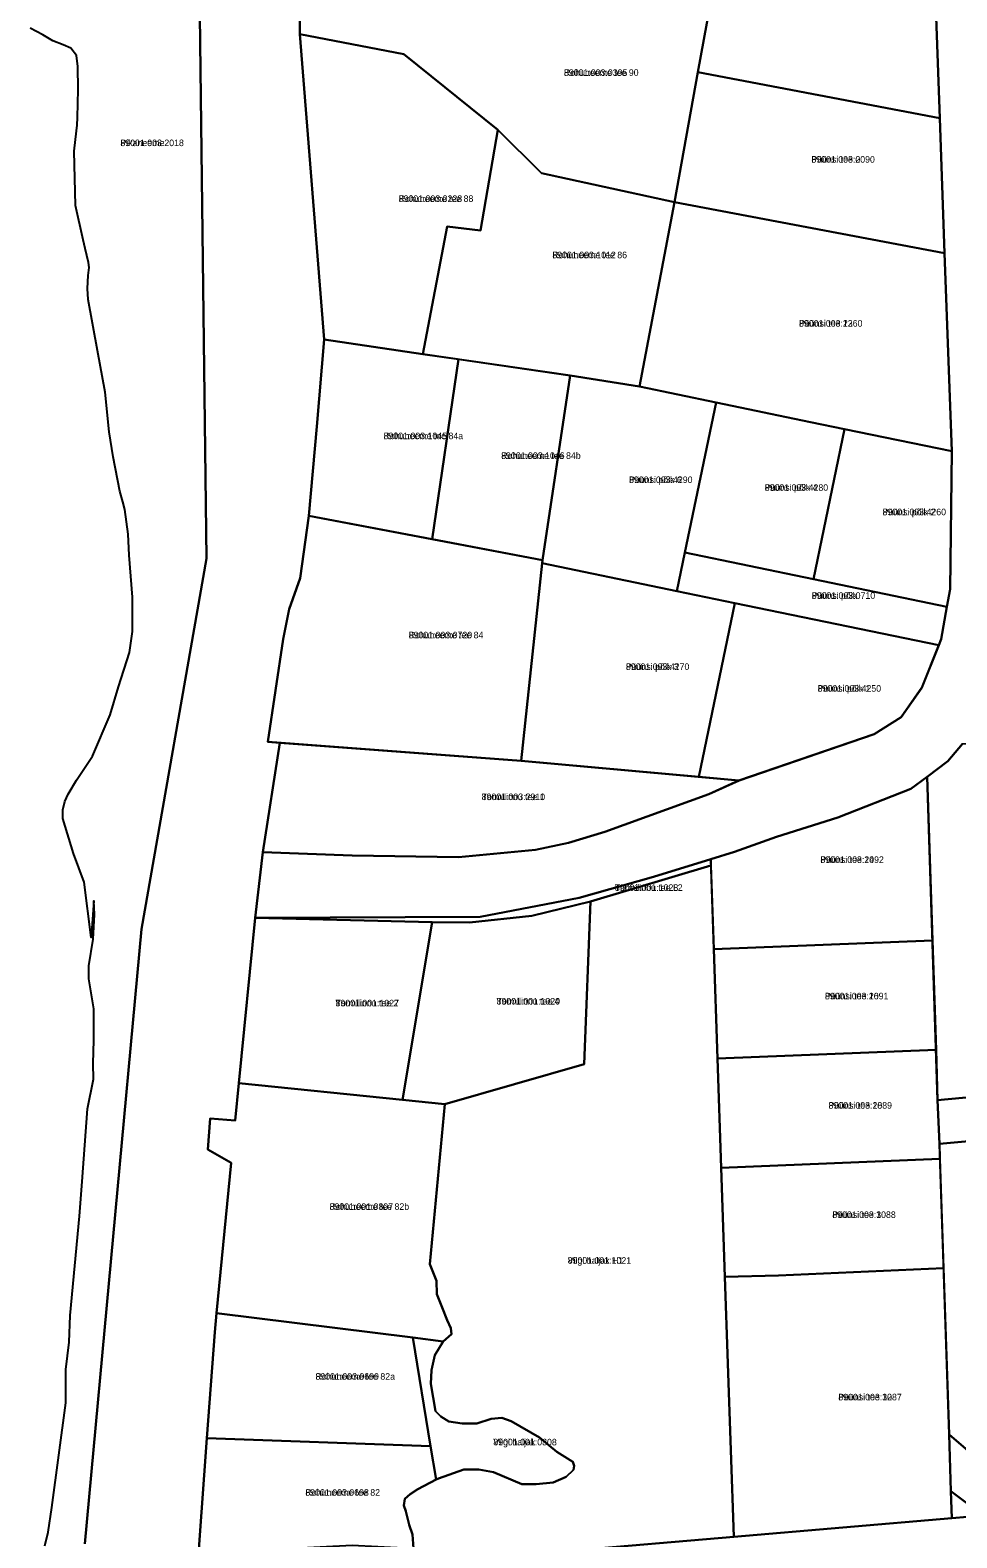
# Model space of a CAD drawing. Extents: x 526849 to 562296, y 6591741 to 6618546.
# Drawn here: x 544904.7 to 545116.6, y 6601222.5 to 6601567.1 of the extents above; entities that cross this region are included whole.
import ezdxf

# ---------------------------------------------------------------- set-up
doc = ezdxf.new("R2010")
doc.units = 0
for name, color, linetype in [('L_AADRESS', 7, 'Continuous'), ('PIIR', 7, 'Continuous'), ('TUNNUS', 7, 'Continuous')]:
    doc.layers.add(name, color=color, linetype=linetype)

msp = doc.modelspace()

# ---------------------------------------------------------------- linework, layer by layer
at = {"layer": 'PIIR'}
for points in [[(544917.24, 6601221.09), (544930.18, 6601361.63), (544945.05, 6601446.36), (544943.56, 6601570.5), (544945.36, 6601601.21), (544952.42, 6601687.05), (544958.45, 6601722.95), (544953.66, 6601829.01)], [(544953.66, 6601829.01), (544958.45, 6601722.95), (544952.42, 6601687.05), (544945.36, 6601601.21), (544943.56, 6601570.5), (544945.05, 6601446.36), (544930.18, 6601361.63), (544917.24, 6601221.09)], [(545117.87, 6601403.98), (545114.48, 6601400.03), (545109.74, 6601396.48), (545106.06, 6601393.72), (545089.33, 6601387.17), (545075.37, 6601382.73), (545065.77, 6601379.33), (545060.31, 6601377.63), (545047.2, 6601373.59), (545030.21, 6601368.81), (545007.59, 6601364.42), (544956.17, 6601364.26), (544957.94, 6601379.21), (544978.37, 6601378.47), (545002.65, 6601378.06), (545020.24, 6601379.81), (545027.77, 6601381.36), (545036.06, 6601383.86), (545059.87, 6601392.51), (545066.78, 6601395.64), (545097.69, 6601406.24), (545103.86, 6601410.1), (545108.55, 6601416.84), (545112.45, 6601426.54), (545113.01, 6601427.95), (545114.3, 6601435.35), (545115, 6601439.34), (545115.38, 6601470.87), (545113.73, 6601516.18), (545112.65, 6601547.05), (545111.16, 6601589.11)], [(544966.24, 6601585.53), (544966.36, 6601566.24), (544971.94, 6601496.4), (544970.29, 6601476.52), (544968.44, 6601456.13), (544966.44, 6601441.84), (544963.92, 6601434.79), (544962.57, 6601427.94), (544959.08, 6601404.43), (544961.78, 6601404.22), (544957.94, 6601379.21), (544956.17, 6601364.26), (544952.47, 6601326.4), (544951.62, 6601317.89), (544945.91, 6601318.37), (544945.35, 6601311.3), (544950.69, 6601308.22), (544947.36, 6601273.83), (544946.95, 6601269.54), (544945.15, 6601245.31), (544943.26, 6601219.91)], [(544908.09, 6601220.66), (544908.82, 6601223.77), (544909.67, 6601229.43), (544912.9, 6601253.33), (544912.89, 6601260.97), (544913.66, 6601267.2), (544913.88, 6601273.36), (544916.05, 6601296.03), (544916.62, 6601303.94), (544917.88, 6601320.54), (544919.24, 6601327.36), (544919.11, 6601330.92), (544919.33, 6601336.28), (544919.26, 6601343.45), (544918.14, 6601350.31), (544918.13, 6601353.25), (544919.15, 6601359.33), (544919.48, 6601364.97), (544919.32, 6601368.1), (544918.7, 6601359.74), (544917.12, 6601372.36), (544914.68, 6601378.96), (544912.21, 6601386.96), (544912.23, 6601388.89), (544912.64, 6601390.83), (544913.39, 6601392.49), (544915.3, 6601395.68), (544918.98, 6601401.21), (544923.04, 6601410.65), (544924.97, 6601417.03), (544927.41, 6601424.86), (544928.16, 6601429.69), (544928.11, 6601437.54), (544927.37, 6601447.15), (544927.18, 6601451.97), (544926.35, 6601457.56), (544925.89, 6601459.36), (544925.25, 6601461.8), (544923.73, 6601469.64), (544922.79, 6601475.34), (544921.89, 6601484.37), (544920.1, 6601493.91), (544918, 6601505.57), (544917.85, 6601508.09), (544917.99, 6601511.05), (544918.21, 6601512.87), (544918.11, 6601514.03), (544917.32, 6601517.21), (544916.86, 6601519.24), (544915.09, 6601527.07), (544914.8, 6601539.48), (544915.33, 6601544.11), (544915.48, 6601545.46), (544915.54, 6601547.19), (544915.75, 6601553.6), (544915.67, 6601558.83), (544915.32, 6601561.35), (544914, 6601563.04), (544912.32, 6601563.83), (544909.89, 6601564.68), (544907.61, 6601566.07), (544904.74, 6601567.6)], [(544992.36, 6601220.04), (544992.14, 6601223.25), (544991.35, 6601225.46), (544990.63, 6601228.63), (544990.17, 6601229.89), (544990.39, 6601231.43), (544991.57, 6601232.51), (544993.38, 6601233.66), (544997.52, 6601235.83), (544998.1, 6601236.08), (545003.89, 6601238.09), (545007.33, 6601238.09), (545010.68, 6601237.51), (545017.13, 6601234.8), (545020.42, 6601234.73), (545024.32, 6601235.15), (545027.29, 6601236.46), (545028.91, 6601238.04), (545029.05, 6601238.99), (545028.78, 6601239.88), (545025.13, 6601242.14), (545021.15, 6601245.47), (545014.67, 6601249.16), (545012.58, 6601249.96), (545010.15, 6601249.69), (545006.83, 6601248.67), (545003.47, 6601248.67), (545000.46, 6601249.11), (544998.61, 6601250.22), (544997.36, 6601251.42), (544996.35, 6601257.69), (544996.51, 6601260.81), (544997.22, 6601264.26), (544999.18, 6601267.41), (545001.02, 6601269.05), (545000.91, 6601270.42), (545000.03, 6601272.22), (544998.9, 6601275.18), (544997.67, 6601278.22), (544997.6, 6601281.23), (544996.09, 6601285.03), (544999.56, 6601321.6), (545031.38, 6601330.78), (545032.85, 6601367.98), (545060.36, 6601376.18), (545061.02, 6601357.07), (545061.83, 6601332.1), (545062.67, 6601307.1), (545063.55, 6601282.13), (545065.58, 6601222.71), (544990.42, 6601216.36)], [(544990.42, 6601216.36), (545065.58, 6601222.71), (545115.38, 6601226.98), (545122.59, 6601227.59), (545130.66, 6601216.72)]]:
    msp.add_lwpolyline(points, dxfattribs=at)
for points in [[(545111.16, 6601589.11), (545112.65, 6601547.05), (545057.37, 6601557.51), (545062.28, 6601584.59)], [(545022.26, 6601585.27), (545062.28, 6601584.59), (545057.37, 6601557.51), (545052, 6601527.86), (545021.64, 6601534.45), (545011.61, 6601544.35), (544990.16, 6601561.63), (544966.36, 6601566.24), (544966.24, 6601585.53)], [(544990.16, 6601561.63), (545011.61, 6601544.35), (545007.64, 6601521.38), (545000.04, 6601522.27), (544994.48, 6601493.11), (544971.94, 6601496.4), (544966.36, 6601566.24)], [(545112.65, 6601547.05), (545113.73, 6601516.18), (545052, 6601527.86), (545057.37, 6601557.51)], [(545011.61, 6601544.35), (545021.64, 6601534.45), (545052, 6601527.86), (545044.02, 6601485.66), (545028.19, 6601488.2), (544994.48, 6601493.11), (545000.04, 6601522.27), (545007.64, 6601521.38)], [(545044.02, 6601485.66), (545052, 6601527.86), (545113.73, 6601516.18), (545115.38, 6601470.87), (545090.88, 6601475.93), (545083.14, 6601477.54), (545061.51, 6601482.03)], [(544971.94, 6601496.4), (544994.48, 6601493.11), (545002.62, 6601491.93), (544996.62, 6601450.78), (544968.44, 6601456.13), (544970.29, 6601476.52)], [(545002.62, 6601491.93), (545028.19, 6601488.2), (545021.84, 6601445.99), (544996.62, 6601450.78)], [(545021.84, 6601445.99), (545028.19, 6601488.2), (545044.02, 6601485.66), (545061.51, 6601482.03), (545054.4, 6601447.75), (545052.57, 6601438.94), (545021.77, 6601445.31)], [(545061.51, 6601482.03), (545083.14, 6601477.54), (545090.88, 6601475.93), (545083.77, 6601441.66), (545054.4, 6601447.75)], [(545090.88, 6601475.93), (545115.38, 6601470.87), (545115, 6601439.34), (545114.3, 6601435.35), (545083.77, 6601441.66)], [(545021.77, 6601445.31), (545016.96, 6601400.1), (544959.08, 6601404.43), (544962.57, 6601427.94), (544963.92, 6601434.79), (544966.44, 6601441.84), (544968.44, 6601456.13), (545021.84, 6601445.99)], [(545052.57, 6601438.94), (545054.4, 6601447.75), (545083.77, 6601441.66), (545114.3, 6601435.35), (545113.01, 6601427.95), (545112.42, 6601426.55), (545065.81, 6601436.19)], [(545057.58, 6601396.47), (545016.96, 6601400.1), (545021.77, 6601445.31), (545052.57, 6601438.94), (545065.81, 6601436.19)], [(545057.58, 6601396.47), (545065.81, 6601436.19), (545112.42, 6601426.55), (545108.52, 6601416.85), (545103.83, 6601410.11), (545097.65, 6601406.25), (545066.75, 6601395.65)], [(544957.94, 6601379.21), (544961.78, 6601404.22), (545016.96, 6601400.1), (545066.75, 6601395.65), (545059.87, 6601392.51), (545036.06, 6601383.86), (545027.77, 6601381.36), (545020.24, 6601379.81), (545002.65, 6601378.06), (544978.37, 6601378.47)], [(545109.74, 6601396.48), (545114.48, 6601400.03), (545117.87, 6601403.98), (545124.46, 6601404.08), (545127.46, 6601404.02), (545124.89, 6601372.21), (545126.1, 6601363.76), (545124.74, 6601346.89), (545125.99, 6601323.84), (545112.16, 6601322.53)], [(545109.74, 6601396.48), (545110.98, 6601359.07), (545061.02, 6601357.07), (545060.31, 6601377.63), (545065.77, 6601379.33), (545075.37, 6601382.73), (545089.33, 6601387.17), (545106.06, 6601393.72)], [(544996.6, 6601363.27), (544956.17, 6601364.26), (545007.59, 6601364.42), (545030.21, 6601368.81), (545047.2, 6601373.59), (545060.31, 6601377.63), (545060.36, 6601376.18), (545032.85, 6601367.98), (545019.44, 6601364.71), (545005.15, 6601363.15)], [(544989.85, 6601322.61), (544996.6, 6601363.27), (545005.15, 6601363.15), (545019.44, 6601364.71), (545032.85, 6601367.98), (545031.38, 6601330.78), (544999.56, 6601321.6)], [(544952.47, 6601326.4), (544956.17, 6601364.26), (544996.6, 6601363.27), (544989.85, 6601322.61)], [(545110.98, 6601359.07), (545111.82, 6601334.09), (545061.83, 6601332.1), (545061.02, 6601357.07)], [(545111.82, 6601334.09), (545112.16, 6601322.53), (545112.56, 6601312.54), (545112.65, 6601309.12), (545062.67, 6601307.1), (545061.83, 6601332.1)], [(545334.27, 6601328.35), (545333.81, 6601317.68), (545308.82, 6601316.59), (545283.95, 6601315.49), (545258.81, 6601314.43), (545234.13, 6601313.35), (545209.06, 6601312.18), (545183.94, 6601311.21), (545159.28, 6601310.16), (545134.1, 6601309.04), (545128.13, 6601308.78), (545127.85, 6601313.99), (545125.21, 6601313.74), (545112.56, 6601312.54), (545112.16, 6601322.53), (545125.99, 6601323.84), (545126.14, 6601321.06), (545159.12, 6601321.87), (545183.85, 6601322.98), (545208.81, 6601323.89), (545234.29, 6601324.83), (545258.88, 6601325.53), (545283.58, 6601326.33), (545308.27, 6601327.35)], [(544951.62, 6601317.89), (544952.47, 6601326.4), (544989.85, 6601322.61), (544999.56, 6601321.6), (544996.09, 6601285.03), (544997.6, 6601281.23), (544997.67, 6601278.22), (544998.9, 6601275.18), (545000.03, 6601272.22), (545000.91, 6601270.42), (545001.02, 6601269.05), (544999.18, 6601267.41), (544992.18, 6601268.28), (544947.36, 6601273.83), (544950.69, 6601308.22), (544945.35, 6601311.3), (544945.91, 6601318.37)], [(545125.21, 6601313.74), (545127.85, 6601313.99), (545128.13, 6601308.78), (545129.37, 6601269.04), (545129.81, 6601255.05), (545125.81, 6601254.9), (545126.12, 6601245), (545130.12, 6601245.02), (545130.46, 6601234.18), (545121.25, 6601240.53), (545114.82, 6601246.09), (545112.56, 6601312.54)], [(545112.65, 6601309.12), (545113.48, 6601284.14), (545075.8, 6601282.48), (545063.55, 6601282.13), (545062.67, 6601307.1)], [(545113.48, 6601284.14), (545114.82, 6601246.09), (545115.2, 6601233.19), (545115.38, 6601226.98), (545065.58, 6601222.71), (545063.55, 6601282.13), (545075.8, 6601282.48)], [(544947.36, 6601273.83), (544992.19, 6601268.28), (544996.27, 6601243.45), (544945.15, 6601245.31), (544946.95, 6601269.54)], [(545010.68, 6601237.51), (545007.33, 6601238.09), (545003.89, 6601238.09), (544998.1, 6601236.08), (544997.52, 6601235.83), (544996.27, 6601243.45), (544992.18, 6601268.28), (544999.18, 6601267.41), (544997.22, 6601264.26), (544996.51, 6601260.81), (544996.35, 6601257.69), (544997.36, 6601251.42), (544998.61, 6601250.22), (545000.46, 6601249.11), (545003.47, 6601248.67), (545006.83, 6601248.67), (545010.15, 6601249.69), (545012.58, 6601249.96), (545014.67, 6601249.16), (545021.15, 6601245.47), (545025.13, 6601242.14), (545028.78, 6601239.88), (545029.05, 6601238.99), (545028.91, 6601238.04), (545027.29, 6601236.46), (545024.32, 6601235.15), (545020.42, 6601234.73), (545017.13, 6601234.8)], [(544945.15, 6601245.31), (544996.27, 6601243.45), (544997.52, 6601235.83), (544993.38, 6601233.66), (544991.57, 6601232.51), (544990.39, 6601231.43), (544990.17, 6601229.89), (544990.63, 6601228.63), (544991.35, 6601225.46), (544992.14, 6601223.25), (544992.36, 6601220.04), (544990.05, 6601220.15), (544978.32, 6601220.74), (544943.19, 6601218.92), (544943.26, 6601219.91)], [(545337.28, 6601226.86), (545328.13, 6601227), (545282.64, 6601222.28), (545241.44, 6601217.26), (545212.59, 6601216.84), (545187.84, 6601216.97), (545162.51, 6601216.59), (545130.66, 6601216.72), (545122.59, 6601227.59), (545115.2, 6601233.19), (545114.82, 6601246.09), (545121.25, 6601240.53), (545130.46, 6601234.18), (545130.55, 6601231.32), (545136.85, 6601228.93), (545162.47, 6601230.01), (545187.27, 6601231.07), (545212.18, 6601232.16), (545236.99, 6601233.26), (545262.31, 6601234.39), (545287.11, 6601235.56), (545311.51, 6601236.68), (545336.86, 6601237.94)], [(545122.59, 6601227.59), (545115.38, 6601226.98), (545115.2, 6601233.19)]]:
    msp.add_lwpolyline(points, close=True, dxfattribs=at)

# ---------------------------------------------------------------- texts
at = {"layer": 'L_AADRESS'}
for s, p in [('Rohuneeme tee 90', (545026.75, 6601556.7)), ('Pikaneeme', (544925.37, 6601540.64)), ('Püünsi tee 20', (545083.32, 6601536.85)), ('Rohuneeme tee 88', (544988.98, 6601527.88)), ('Rohuneeme tee 86', (545024.11, 6601515.01)), ('Püünsi tee 22', (545080.48, 6601499.37)), ('Rohuneeme tee 84a', (544985.53, 6601473.65)), ('Rohuneeme tee 84b', (545012.4, 6601469.14)), ('Püünsi põik 6', (545041.64, 6601463.62)), ('Püünsi põik 4', (545072.64, 6601461.84)), ('Püünsi põik 2', (545099.58, 6601456.26)), ('Püünsi põik', (545083.39, 6601437.15)), ('Rohuneeme tee 84', (544991.27, 6601428.12)), ('Püünsi põik 3', (545040.91, 6601420.89)), ('Püünsi põik 1', (545084.74, 6601415.92)), ('Tormilinnu tee 1', (545007.94, 6601391.14)), ('Püünsi tee 24', (545085.37, 6601376.78)), ('Tormilinnu tee L2', (545038.38, 6601370.39)), ('Tormilinnu tee 2', (544974.54, 6601343.99)), ('Tormilinnu tee 4', (545011.35, 6601344.41)), ('Püünsi tee 26', (545086.41, 6601345.59)), ('Püünsi tee 28', (545087.23, 6601320.6)), ('Rohuneeme tee 82b', (544973.19, 6601297.47)), ('Püünsi tee 30', (545088.09, 6601295.62)), ('Viigi haljak H1', (545027.61, 6601285.15)), ('Rohuneeme tee 82a', (544969.96, 6601258.64)), ('Püünsi tee 32', (545089.46, 6601253.92)), ('Viigi haljak', (545010.61, 6601243.63)), ('Rohuneeme tee 82', (544967.65, 6601232.12))]:
    msp.add_text(s, height=1.5, dxfattribs=at).set_placement(p)
at = {"layer": 'TUNNUS'}
for s, p in [('89001:003:0395', (545026.75, 6601556.7)), ('89001:003:2018', (544925.37, 6601540.64)), ('89001:003:0090', (545083.32, 6601536.85)), ('89001:003:0228', (544988.98, 6601527.88)), ('89001:003:1012', (545024.11, 6601515.01)), ('89001:003:1360', (545080.48, 6601499.37)), ('89001:003:1045', (544985.53, 6601473.65)), ('89001:003:1046', (545012.4, 6601469.14)), ('89001:003:4290', (545041.64, 6601463.62)), ('89001:003:4280', (545072.64, 6601461.84)), ('89001:003:4260', (545099.58, 6601456.26)), ('89001:003:0710', (545083.39, 6601437.15)), ('89001:003:0720', (544991.27, 6601428.12)), ('89001:003:4270', (545040.91, 6601420.89)), ('89001:003:4250', (545084.74, 6601415.92)), ('89001:003:2910', (545007.94, 6601391.14)), ('89001:003:1092', (545085.37, 6601376.78)), ('89001:001:1028', (545038.38, 6601370.39)), ('89001:001:1027', (544974.54, 6601343.99)), ('89001:001:1020', (545011.35, 6601344.41)), ('89001:003:1091', (545086.41, 6601345.59)), ('89001:003:1089', (545087.23, 6601320.6)), ('89001:001:0807', (544973.19, 6601297.47)), ('89001:003:1088', (545088.09, 6601295.62)), ('89001:001:1021', (545027.61, 6601285.15)), ('89001:003:0699', (544969.96, 6601258.64)), ('89001:003:1087', (545089.46, 6601253.92)), ('89001:001:0808', (545010.61, 6601243.63)), ('89001:003:0698', (544967.65, 6601232.12))]:
    msp.add_text(s, height=1.5, dxfattribs=at).set_placement(p)

doc.saveas('drawing.dxf')
